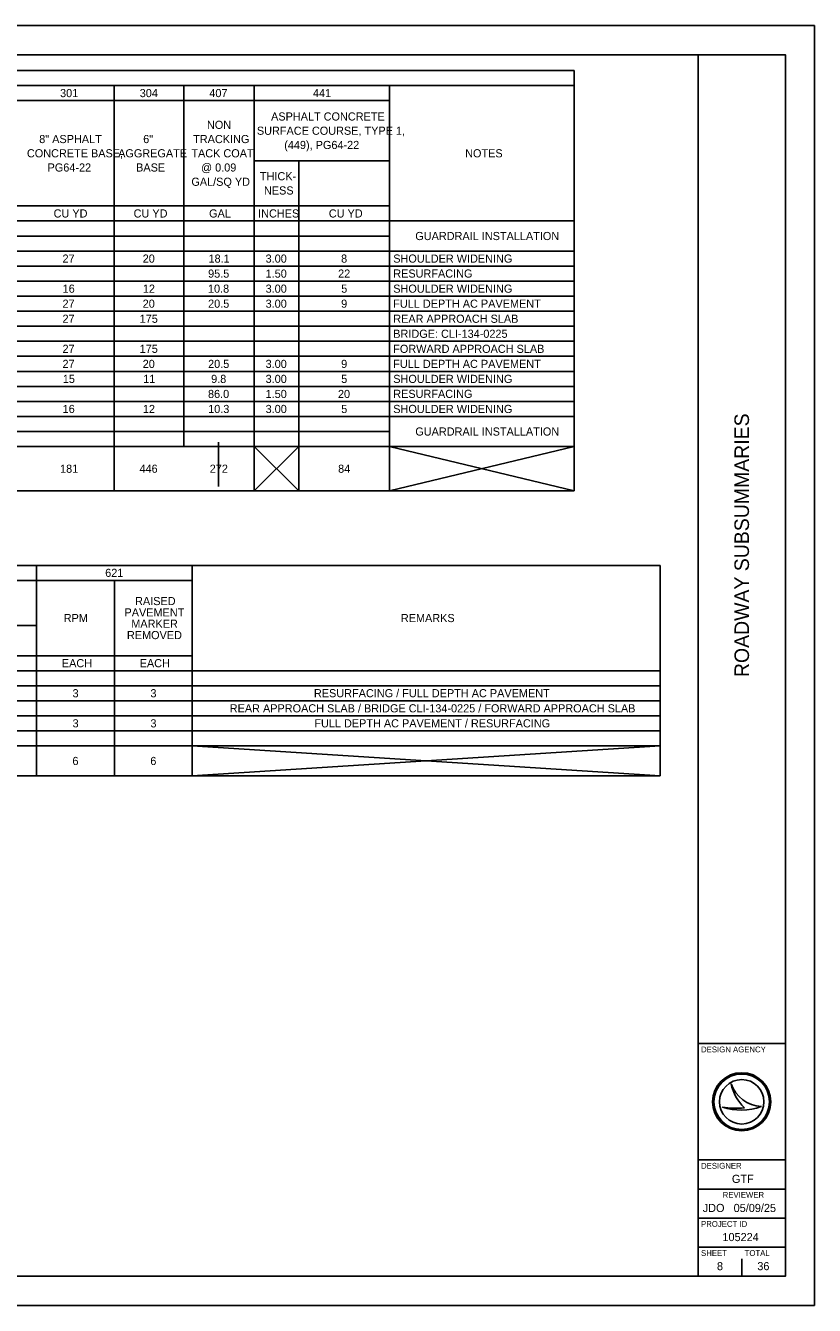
# Model space of a CAD drawing. Extents: x -27.3 to 69.3, y 0 to 30.
# Drawn here: x 20.43 to 34, y 0 to 22 of the extents above; entities that cross this region are included whole.
import ezdxf

# ---------------------------------------------------------------- set-up
doc = ezdxf.new("R2010")
doc.units = 0
for name, color, linetype in [('Default', 7, 'Continuous'), ('SH_Border', 7, 'Continuous'), ('SH_Cut_Line', 7, 'Continuous'), ('SH_Data', 7, 'Continuous')]:
    doc.layers.add(name, color=color, linetype=linetype)

msp = doc.modelspace()

# ---------------------------------------------------------------- linework, layer by layer
at = {"layer": 'Default'}
for p, q in [((1.762, 21.228), (29.869, 21.228)), ((29.869, 21.228), (29.869, 14.003)), ((1.762, 20.969), (29.869, 20.969)), ((21.958, 20.969), (21.958, 14.003)), ((23.154, 20.969), (23.154, 14.763)), ((24.366, 20.969), (24.366, 14.003)), ((26.692, 20.969), (26.692, 14.003)), ((8.56, 20.71), (26.692, 20.71)), ((24.366, 19.676), (26.692, 19.676)), ((25.136, 19.676), (25.136, 14.003)), ((3.416, 18.9), (26.692, 18.9)), ((1.762, 18.642), (29.869, 18.642)), ((1.762, 18.383), (26.692, 18.383)), ((1.762, 18.125), (29.869, 18.125)), ((1.762, 17.866), (29.869, 17.866)), ((1.762, 17.608), (29.869, 17.608)), ((1.762, 17.349), (29.869, 17.349)), ((1.762, 17.09), (29.869, 17.09)), ((1.762, 16.832), (29.869, 16.832)), ((1.762, 16.573), (29.869, 16.573)), ((1.762, 16.315), (29.869, 16.315)), ((1.762, 16.056), (29.869, 16.056)), ((1.762, 15.798), (29.869, 15.798)), ((1.762, 15.539), (29.869, 15.539)), ((1.762, 15.28), (29.869, 15.28)), ((1.762, 15.022), (26.692, 15.022)), ((1.762, 14.763), (26.692, 14.763)), ((23.75, 14.839), (23.75, 14.079)), ((24.366, 14.003), (25.136, 14.763)), ((24.366, 14.763), (25.136, 14.003)), ((26.692, 14.003), (29.869, 14.763)), ((26.692, 14.763), (29.869, 14.003)), ((26.692, 14.763), (29.869, 14.763)), ((1.762, 14.003), (29.869, 14.003)), ((1.762, 12.721), (31.345, 12.721)), ((20.622, 12.721), (20.622, 9.101)), ((23.299, 12.721), (23.299, 9.101)), ((31.345, 12.721), (31.345, 9.101)), ((8.576, 12.462), (23.299, 12.462)), ((21.961, 12.462), (21.961, 9.101)), ((9.915, 11.686), (20.622, 11.686)), ((3.161, 11.169), (23.299, 11.169)), ((1.762, 10.911), (23.299, 10.911)), ((23.299, 10.911), (31.345, 10.911)), ((1.762, 10.652), (31.345, 10.652)), ((1.762, 10.393), (31.345, 10.393)), ((1.762, 10.135), (31.345, 10.135)), ((1.762, 9.876), (31.345, 9.876)), ((1.762, 9.618), (31.345, 9.618)), ((23.299, 9.101), (31.345, 9.618)), ((23.299, 9.618), (31.345, 9.101)), ((1.762, 9.101), (31.345, 9.101))]:
    msp.add_line(p, q, dxfattribs=at)
at = {"layer": 'SH_Border'}
for p, q in [((32, 0.5), (32, 21.5)), ((32, 4.5), (33.5, 4.5)), ((32, 2.5), (33.5, 2.5)), ((32, 2), (33.5, 2)), ((32, 1.5), (33.5, 1.5)), ((32, 1), (33.5, 1))]:
    msp.add_line(p, q, dxfattribs=at)
msp.add_lwpolyline([(1.5, 21.5), (33.5, 21.5), (33.5, 0.5), (1.5, 0.5)], close=True, dxfattribs=at)
at = {"layer": 'SH_Cut_Line'}
msp.add_lwpolyline([(0, 0), (34, 0), (34, 22), (0, 22)], close=True, dxfattribs=at)
at = {"layer": 'SH_Data'}
for p, q in [((32.567, 3.81), (32.567, 3.81)), ((32.417, 3.41), (32.417, 3.41)), ((32.75, 3.5), (32.75, 3.5)), ((33.087, 3.419), (33.087, 3.419)), ((32.375, 0.675), (32.375, 0.675)), ((32.75, 0.5), (32.75, 0.8))]:
    msp.add_line(p, q, dxfattribs=at)
for radius in [0.5, 0.477, 0.477, 0.382]:
    msp.add_circle((32.75, 3.5), radius, dxfattribs=at)
for centre, radius, start, end in [((33.116, 3.998), 0.58, 198.9257, 198.9319), ((33.347, 3.97), 0.796, 191.6379, 191.6421), ((33.116, 3.998), 0.58, 198.9319, 267.1657), ((33.347, 3.97), 0.796, 191.6421, 226.0947), ((32.739, 4.37), 1.013, 251.4576, 290.0832), ((32.648, 4.654), 1.266, 259.4964, 259.4995), ((32.739, 4.37), 1.013, 251.4527, 251.4576), ((32.648, 4.654), 1.266, 259.4995, 276.6672)]:
    msp.add_arc(centre, radius, start, end, dxfattribs=at)

# ---------------------------------------------------------------- texts
at = {"layer": 'Default'}
for s, height, p in [('301', 0.1399, (21.027, 20.77)), ('304', 0.1399, (22.397, 20.77)), ('407', 0.1399, (23.594, 20.77)), ('441', 0.1399, (25.376, 20.77)), ('ASPHALT CONCRETE ', 0.13993, (24.656, 20.368)), ('NON ', 0.1399, (23.553, 20.225)), ('SURFACE COURSE, TYPE 1, ', 0.13993, (24.412, 20.123)), ('8" ASPHALT ', 0.13993, (20.669, 19.98)), ('6" ', 0.1399, (22.457, 19.98)), ('TRACKING ', 0.1399, (23.316, 19.98)), ('(449), PG64-22', 0.13993, (24.882, 19.878)), ('CONCRETE BASE, ', 0.13993, (20.457, 19.735)), ('AGGREGATE ', 0.1399, (22.026, 19.735)), ('TACK COAT ', 0.1399, (23.285, 19.735)), ('NOTES', 0.1399, (27.993, 19.735)), ('PG64-22', 0.1399, (20.812, 19.491)), ('BASE', 0.1399, (22.335, 19.491)), ('@ 0.09 ', 0.1399, (23.452, 19.491)), ('GAL/SQ YD', 0.1399, (23.285, 19.246)), ('THICK-', 0.1399, (24.464, 19.341)), ('NESS', 0.1399, (24.534, 19.096)), ('CU YD', 0.1399, (20.916, 18.701)), ('CU YD', 0.1399, (22.292, 18.701)), ('GAL', 0.1399, (23.59, 18.701)), ('INCHES', 0.1399, (24.433, 18.701)), ('CU YD', 0.1399, (25.649, 18.701)), ('GUARDRAIL INSTALLATION', 0.13993, (27.136, 18.313)), ('27', 0.1399, (21.069, 17.925)), ('20', 0.1399, (22.448, 17.925)), ('18.1', 0.1399, (23.58, 17.925)), ('3.00', 0.1399, (24.562, 17.925)), ('8', 0.14, (25.86, 17.925)), ('SHOULDER WIDENING', 0.13993, (26.757, 17.925)), ('95.5', 0.1399, (23.573, 17.667)), ('1.50', 0.1399, (24.562, 17.667)), ('22', 0.1399, (25.809, 17.667)), ('RESURFACING', 0.13993, (26.757, 17.668)), ('16', 0.1399, (21.071, 17.408)), ('12', 0.1399, (22.451, 17.408)), ('10.8', 0.1399, (23.571, 17.408)), ('3.00', 0.1399, (24.562, 17.408)), ('5', 0.14, (25.862, 17.408)), ('SHOULDER WIDENING', 0.13993, (26.757, 17.408)), ('27', 0.1399, (21.069, 17.15)), ('20', 0.1399, (22.448, 17.15)), ('20.5', 0.1399, (23.573, 17.15)), ('3.00', 0.1399, (24.562, 17.15)), ('9', 0.14, (25.861, 17.15)), ('FULL DEPTH AC PAVEMENT', 0.13993, (26.757, 17.15)), ('27', 0.1399, (21.069, 16.891)), ('175', 0.1399, (22.396, 16.891)), ('REAR APPROACH SLAB', 0.13993, (26.757, 16.891)), ('BRIDGE: CLI-134-0225', 0.13993, (26.757, 16.633)), ('27', 0.1399, (21.069, 16.374)), ('175', 0.1399, (22.396, 16.374)), ('FORWARD APPROACH SLAB', 0.13993, (26.757, 16.374)), ('27', 0.1399, (21.069, 16.115)), ('20', 0.1399, (22.448, 16.115)), ('20.5', 0.1399, (23.573, 16.115)), ('3.00', 0.1399, (24.562, 16.115)), ('9', 0.14, (25.861, 16.115)), ('FULL DEPTH AC PAVEMENT', 0.13993, (26.757, 16.115)), ('15', 0.1399, (21.074, 15.857)), ('11', 0.1399, (22.457, 15.857)), ('9.8', 0.1399, (23.625, 15.857)), ('3.00', 0.1399, (24.562, 15.857)), ('5', 0.14, (25.862, 15.857)), ('SHOULDER WIDENING', 0.13993, (26.757, 15.857)), ('86.0', 0.1399, (23.571, 15.598)), ('1.50', 0.1399, (24.562, 15.598)), ('20', 0.1399, (25.806, 15.598)), ('RESURFACING', 0.13993, (26.757, 15.6)), ('16', 0.1399, (21.071, 15.34)), ('12', 0.1399, (22.451, 15.34)), ('10.3', 0.1399, (23.574, 15.34)), ('3.00', 0.1399, (24.562, 15.34)), ('5', 0.14, (25.862, 15.34)), ('SHOULDER WIDENING', 0.13993, (26.757, 15.34)), ('GUARDRAIL INSTALLATION', 0.13993, (27.136, 14.952)), ('181', 0.1399, (21.027, 14.313)), ('446', 0.1399, (22.393, 14.313)), ('272', 0.1399, (23.601, 14.313)), ('84', 0.1399, (25.809, 14.313)), ('621', 0.1399, (21.803, 12.523)), ('RAISED ', 0.1399, (22.317, 12.038)), ('RPM', 0.1399, (21.09, 11.746)), ('PAVEMENT ', 0.1399, (22.135, 11.843)), ('REMARKS', 0.1399, (26.888, 11.746)), ('MARKER ', 0.1399, (22.252, 11.648)), ('REMOVED', 0.1399, (22.177, 11.453)), ('EACH', 0.1399, (21.058, 10.97)), ('EACH', 0.1399, (22.396, 10.97)), ('3', 0.14, (21.242, 10.453)), ('3', 0.14, (22.581, 10.453)), ('RESURFACING / FULL DEPTH AC PAVEMENT', 0.13993, (25.393, 10.454)), ('REAR APPROACH SLAB / BRIDGE CLI-134-0225 / FORWARD APPROACH SLAB', 0.13993, (23.945, 10.194)), ('3', 0.14, (21.242, 9.936)), ('3', 0.14, (22.581, 9.936)), ('FULL DEPTH AC PAVEMENT / RESURFACING', 0.13993, (25.4, 9.936)), ('6', 0.14, (21.24, 9.289)), ('6', 0.14, (22.579, 9.289))]:
    msp.add_text(s, height=height, dxfattribs=at).set_placement(p)
at = {"layer": 'SH_Data'}
msp.add_text('ROADWAY SUBSUMMARIES', height=0.25, rotation=90, dxfattribs=at).set_placement((32.875, 10.801))
for s, height, p in [('DESIGN AGENCY', 0.1, (32.05, 4.35)), ('DESIGNER', 0.1, (32.05, 2.35)), ('GTF', 0.14, (32.581, 2.105)), ('REVIEWER', 0.1, (32.422, 1.85)), ('JDO', 0.14, (32.079, 1.605)), ('05/09/25', 0.14, (32.611, 1.605)), ('PROJECT ID', 0.1, (32.05, 1.35)), ('105224', 0.14, (32.418, 1.105)), ('SHEET', 0.1, (32.05, 0.85)), ('TOTAL', 0.1, (32.8, 0.85)), ('8', 0.14, (32.324, 0.605)), ('36', 0.14, (33.018, 0.605))]:
    msp.add_text(s, height=height, dxfattribs=at).set_placement(p)

doc.saveas('drawing.dxf')
